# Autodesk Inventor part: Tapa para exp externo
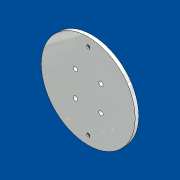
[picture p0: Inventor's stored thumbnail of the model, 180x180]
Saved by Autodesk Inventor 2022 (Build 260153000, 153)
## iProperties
Created: 2022-05
Part Number: Tapa para exp externo
Material: Generic
Document SubType Name: Modeling
Designer: Daniel
Density: 1 g/cm^3
Appearance: Default
Author: Daniel
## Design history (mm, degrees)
sketch "Sketch1" dims "d0" = 25
  geometry: L1 (0, 0)-(15.112, 15.112); L2 (0, 0)-(21.372, 0); L3 (0, 0)-(-15.112, 15.112); L4 (0, 0)-(-15.112, -15.112); L5 (0, 0)-(15.112, -15.112); L6 (-26.416, -15.251)-(-26.416, -12.249) reference; L7 (-26.416, -12.249)-(-23.816, -10.748) reference; L8 (-23.816, -10.748)-(-21.216, -12.249) reference; L9 (-21.216, -12.249)-(-21.216, -15.251) reference; L10 (-21.216, -15.251)-(-23.816, -16.752) reference; L11 (-23.816, -16.752)-(-26.416, -15.251) reference; L12 (26.416, -15.251)-(23.816, -16.752) reference; L13 (23.816, -16.752)-(21.216, -15.251) reference; L14 (21.216, -15.251)-(21.216, -12.249) reference; L15 (21.216, -12.249)-(23.816, -10.748) reference; L16 (23.816, -10.748)-(26.416, -12.249) reference; L17 (26.416, -12.249)-(26.416, -15.251) reference; L18 (0, 30.502)-(2.6, 29.001) reference; L19 (2.6, 29.001)-(2.6, 25.999) reference; L20 (2.6, 25.999)-(0, 24.498) reference; L21 (0, 24.498)-(-2.6, 25.999) reference; L22 (-2.6, 25.999)-(-2.6, 29.001) reference; L23 (-2.6, 29.001)-(0, 30.502) reference; L24 (28.186, -11.654)-(25.816, -10.286) reference; L25 (21.816, -17.214)-(24.186, -18.582) reference; L26 (-24.186, -18.582)-(-21.816, -17.214) reference; L27 (-25.816, -10.286)-(-28.186, -11.654) reference; L28 (-4, 30.237)-(-4, 27.5) reference; L29 (4, 27.5)-(4, 30.237) reference; C1 r 32.5 at (0, 0) reference; C2 r 1.5 at (8.839, 8.839); C3 r 1.5 at (-8.839, 8.839); C4 r 1.5 at (-8.839, -8.839); C5 r 1.5 at (8.839, -8.839); A1 r 30.5 centre (0, 0) between (28.186, -11.654) and (4, 30.237) reference; A2 r 30.5 centre (0, 0) between (-24.186, -18.582) and (24.186, -18.582) reference; A3 r 30.5 centre (0, 0) between (-4, 30.237) and (-28.186, -11.654) reference; A4 r 4 centre (23.816, -13.75) between (25.816, -10.286) and (21.816, -17.214) reference; A5 r 4 centre (-23.816, -13.75) between (-21.816, -17.214) and (-25.816, -10.286) reference; A6 r 4 centre (0, 27.5) between (-4, 27.5) and (4, 27.5) reference; 1 further point
  constraints: 10 end point, 4 centre point, 4 point on line, 1 equal length, 1 horizontal, 24 other
  dimensions: "d1" = 45 deg angle of L2 L1; "d2" = 3 diameter of C2; "d5" = 360 deg dimension on point (0, 0) L1.end (derived)
extrude "Extrusion1" new body sketch "Sketch1" distance "d7" = 2.5; taper "d8" = 0 deg
sketch "Boceto3"
  geometry: C1 r 1.5 at (0, -26.5) reference; C2 r 1.5 at (0, 26.5) reference; 3 further points
  constraints: 2 centre point, 2 coincident, 4 other
hole "Agujero2" sketch "Boceto3" at (0, -26.5), (0, 26.5) diameter "d16" = 2.5; stored, may be unused: countersink angle "d20" = 90 deg, drill point angle "d22" = 118 deg; dims "d17" = 6, "d18" = 6.3, "d19" = 2, "d21" = 8
body "Solid1"
node "Reference1"
